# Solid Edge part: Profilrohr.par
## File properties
Username: bmolnar
Dokumentum tartalom típus: 0
Author: bmolnar
Last saved by: bmolnar
Revision: 85
Sűrűség: 0,000 kg/m^3
Pontosság: 0,990
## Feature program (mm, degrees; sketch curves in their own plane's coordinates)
base feature "unnamed BaseFeature 1"
thread "unnamed Thread 1"
thread "Menet_2"  ThreadDepth = 6 mm
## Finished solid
Body 1: solid body, 157 faces, 388 edges, 253 vertices.
  Faces by surface: plane 102, cylinder 41, cone 8, torus 6
  Edges by curve: line 284, circle 92, curve on surface 7, spline 4, intersection 1
Bounding box of the edges (mm; curved faces can reach further): 55.000 x 58.000 x 89.500, from (-27.5, -27.5, 0) to (27.5, 30.5, 89.5).
Cylindrical faces by radius (mm): R1.125 x2, R2.9 x8, R4.283 x4, R4.4 x16, R20 x1, R20.85 x2, R21.1 x2, R22.35 x2, R36.5 x4
Conical faces (half-angle, radius in mm at the cone's reference point): 30 deg R20.325 x2, 45 deg R4.783 x2, 45 deg R21.1 x2, 45 deg R21.35 x2
Toroidal faces (ring radius, tube radius in mm): R20.75 r0.1 x2, R22.15 r0.2 x4
Planar faces by outward normal: +x 9, +y 11, +z 8, -x 9, -y 9, -z 8, oblique 48
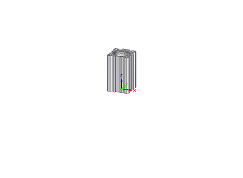
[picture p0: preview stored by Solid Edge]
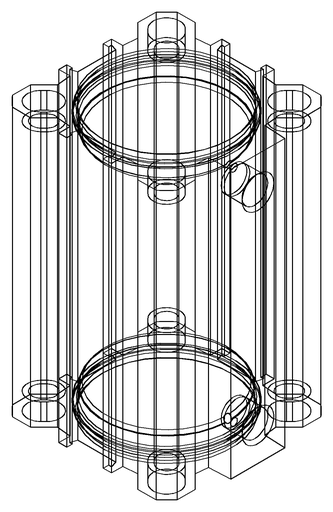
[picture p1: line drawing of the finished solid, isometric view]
